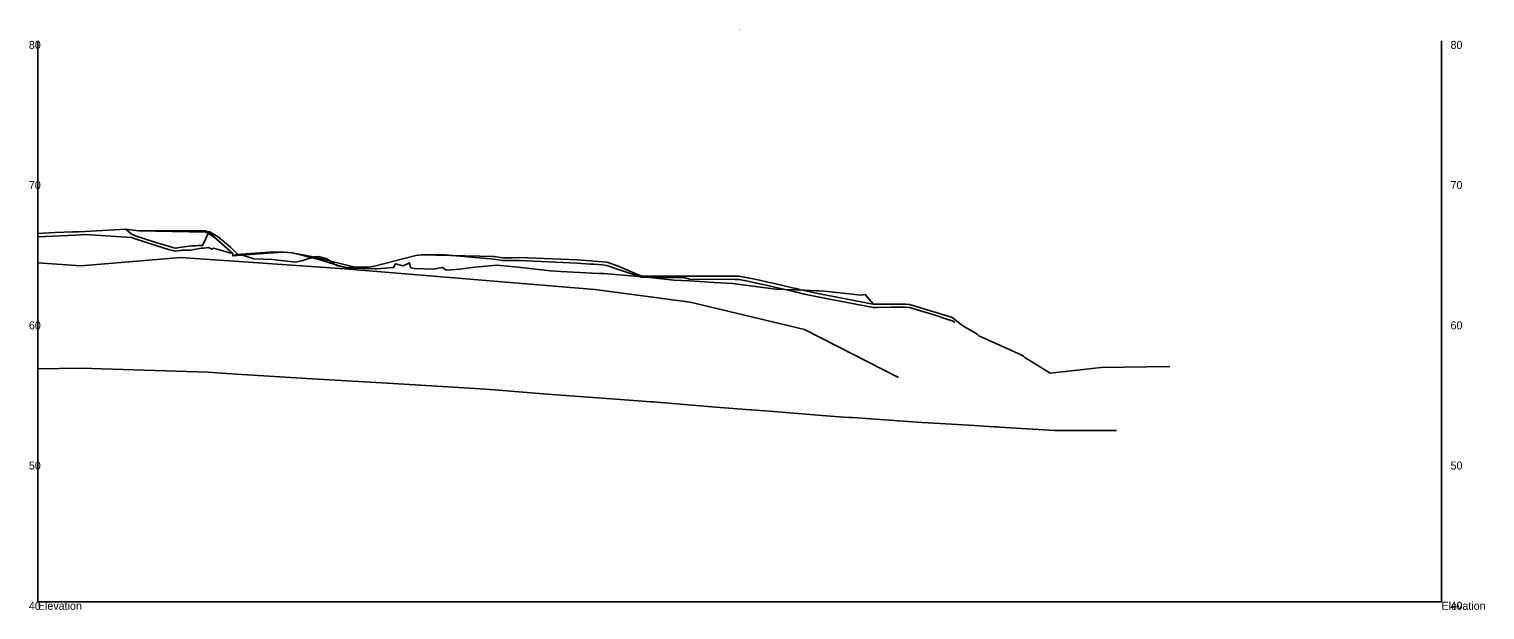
# Model space of a CAD drawing. Extents: x 532503 to 539665, y 6557663 to 6561526.
# Drawn here: x 533984 to 534503, y 6557663 to 6557870 of the extents above; entities that cross this region are included whole.
import ezdxf

# ---------------------------------------------------------------- set-up
doc = ezdxf.new("R2010")
doc.units = 0
for name, color, linetype in [('Default', 7, 'Continuous'), ('lamam', 7, 'Continuous'), ('maapind', 7, 'Continuous'), ('maapind varasem', 7, 'Continuous'), ('P_Profile', 7, 'Continuous'), ('P_SURF_Profile', 7, 'Continuous'), ('vahepiir', 7, 'Continuous')]:
    doc.layers.add(name, color=color, linetype=linetype)

msp = doc.modelspace()

# ---------------------------------------------------------------- linework, layer by layer
at = {"layer": 'Default'}
msp.add_lwpolyline([(533987.25, 6557797.54), (533993.4, 6557797.79), (533999.66, 6557798.05), (534001.76, 6557798.14), (534004.12, 6557798.25), (534018.62, 6557798.99), (534023.1, 6557798.44), (534047.07, 6557798.47), (534049.8, 6557796.71), (534056.65, 6557790.3), (534056.68, 6557789.49), (534069.19, 6557790.51), (534074.73, 6557790.83), (534077.89, 6557790.6), (534084.73, 6557789.27), (534099.76, 6557785.63), (534105.12, 6557785.51), (534107.22, 6557785.86), (534121.92, 6557789.62), (534123.79, 6557789.89), (534149.82, 6557789.25), (534152.87, 6557788.79), (534153.37, 6557788.78), (534153.81, 6557788.78), (534154.39, 6557788.78), (534154.68, 6557788.78), (534155.1, 6557788.78), (534155.7, 6557788.77), (534156, 6557788.77), (534158.87, 6557788.93), (534179.39, 6557788.07), (534184.14, 6557787.73), (534185.28, 6557787.65), (534188.29, 6557787.41), (534189.94, 6557787.27), (534193.7, 6557785.95), (534202.3, 6557782.27), (534210.95, 6557782.27), (534217.57, 6557782.27), (534233.3, 6557782.27), (534237.05, 6557782.27), (534238.75, 6557781.95), (534238.97, 6557781.9), (534243.82, 6557780.93), (534247.71, 6557780.03), (534249.64, 6557779.61), (534256.5, 6557778.02), (534257.4, 6557777.82), (534258.11, 6557777.65), (534259.77, 6557777.27), (534263.84, 6557776.35), (534284.82, 6557772.27), (534285.22, 6557772.27), (534286.49, 6557772.27), (534291.14, 6557772.27), (534293.2, 6557772.27), (534296.46, 6557772.27), (534297.7, 6557772.19), (534312.65, 6557767.65), (534313.28, 6557767.27), (534315.8, 6557765.31), (534317.33, 6557764.23), (534318.38, 6557763.56), (534319.85, 6557762.76), (534320.89, 6557762.22), (534321.17, 6557762.06), (534321.63, 6557761.74), (534321.87, 6557761.54), (534322.22, 6557761.2), (534322.4, 6557760.99), (534337.49, 6557754.26), (534338.42, 6557753.64), (534338.85, 6557753.31), (534347.85, 6557747.74), (534366, 6557749.68), (534390.43, 6557750.08)], dxfattribs=at)
at = {"layer": 'lamam'}
msp.add_lwpolyline([(533987.25, 6557749.22), (534002.59, 6557749.51), (534047.88, 6557748.01), (534054.47, 6557747.61), (534060.04, 6557747.27), (534084.99, 6557745.62), (534113.76, 6557743.95), (534143.01, 6557742.27), (534149.99, 6557741.7), (534154.36, 6557741.36), (534167.27, 6557740.33), (534201.1, 6557737.85), (534205.48, 6557737.52), (534206.7, 6557737.43), (534209.16, 6557737.27), (534228.7, 6557735.62), (534241.05, 6557734.64), (534241.67, 6557734.59), (534252.25, 6557733.73), (534266.68, 6557732.61), (534271.19, 6557732.27), (534276.15, 6557731.92), (534277.48, 6557731.84), (534297.17, 6557730.43), (534302.25, 6557730.16), (534318.99, 6557729.17), (534327.79, 6557728.57), (534328.9, 6557728.51), (534329.73, 6557728.45), (534349.51, 6557727.27), (534352.02, 6557727.27), (534356.77, 6557727.27), (534359.28, 6557727.27), (534366.89, 6557727.27), (534370.27, 6557727.27), (534371.45, 6557727.27)], dxfattribs=at)
at = {"layer": 'maapind'}
msp.add_lwpolyline([(533987.25, 6557797.54), (533993.4, 6557797.79), (533999.66, 6557798.05), (534001.76, 6557798.14), (534004.12, 6557798.25), (534018.62, 6557798.99), (534020.46, 6557797.35), (534020.73, 6557797.2), (534020.96, 6557797.09), (534021.53, 6557796.85), (534022.29, 6557796.57), (534024.83, 6557795.71), (534029.59, 6557794.2), (534033.76, 6557792.94), (534035.32, 6557792.5), (534036.14, 6557792.27), (534039.36, 6557792.74), (534040.35, 6557792.87), (534042.03, 6557793.04), (534043.46, 6557793.13), (534044.32, 6557793.16), (534045.93, 6557793.18), (534048.23, 6557798.17), (534049.17, 6557797.6), (534051.47, 6557796.35), (534055.84, 6557792.64), (534058.32, 6557790.14), (534059.75, 6557789.87), (534064.19, 6557788.48), (534070.85, 6557788.2), (534079.12, 6557787.23), (534081.59, 6557787.85), (534085.7, 6557789.13), (534087.2, 6557789.23), (534090.35, 6557788.5), (534093.61, 6557786.09), (534098.45, 6557785.07), (534107.31, 6557784.92), (534108.03, 6557784.86), (534113.99, 6557785.31), (534114.61, 6557786.69), (534117.37, 6557785.93), (534119.38, 6557786.97), (534119.43, 6557787.09), (534119.46, 6557787.11), (534119.5, 6557787.1), (534120.14, 6557785.27), (534121.37, 6557784.96), (534128.13, 6557784.81), (534131.24, 6557785.39), (534132.86, 6557784.43), (534137.52, 6557784.76), (534142.88, 6557785.47), (534150.78, 6557786.2), (534158.24, 6557785.45), (534169.82, 6557784.13), (534173.53, 6557783.91), (534186.81, 6557783.27), (534188.84, 6557783.19), (534201.14, 6557782.1), (534204.16, 6557781.9), (534213.83, 6557780.82), (534219.47, 6557780.61), (534228.14, 6557780.04), (534234.83, 6557779.62), (534239.19, 6557779.1), (534250.12, 6557777.69), (534260.23, 6557777.26), (534264.55, 6557777.09), (534265.46, 6557777.05), (534268.63, 6557776.81), (534280.55, 6557775.47), (534281.94, 6557775.69), (534284.8, 6557772.4), (534285.22, 6557772.27), (534286.48, 6557772.27), (534291.14, 6557772.27), (534293.2, 6557772.27), (534296.46, 6557772.27), (534297.7, 6557772.19), (534312.65, 6557767.65), (534313.28, 6557767.27), (534315.8, 6557765.31), (534317.33, 6557764.23), (534318.38, 6557763.56), (534319.85, 6557762.76), (534320.89, 6557762.22), (534321.17, 6557762.06), (534321.63, 6557761.74), (534321.87, 6557761.54), (534322.22, 6557761.2), (534322.4, 6557760.99), (534337.49, 6557754.26), (534338.42, 6557753.64), (534338.85, 6557753.31), (534347.85, 6557747.74), (534366, 6557749.68), (534390.43, 6557750.08)], dxfattribs=at)
at = {"layer": 'maapind varasem'}
msp.add_lwpolyline([(533987.25, 6557797.54), (533993.4, 6557797.79), (533999.66, 6557798.05), (534001.76, 6557798.14), (534004.12, 6557798.25), (534018.62, 6557798.99), (534023.1, 6557798.44), (534047.07, 6557798.02), (534049.8, 6557796.37), (534056.65, 6557790.3), (534056.68, 6557789.49), (534069.19, 6557790.51), (534074.73, 6557790.83), (534077.89, 6557790.6), (534084.73, 6557789.27), (534099.76, 6557785.63), (534105.12, 6557785.51), (534107.22, 6557785.86), (534121.92, 6557789.62), (534123.79, 6557789.89), (534149.82, 6557789.25), (534152.87, 6557788.79), (534153.37, 6557788.78), (534153.81, 6557788.78), (534154.39, 6557788.78), (534154.68, 6557788.78), (534155.1, 6557788.78), (534155.7, 6557788.77), (534156, 6557788.77), (534158.87, 6557788.93), (534179.39, 6557788.07), (534184.14, 6557787.73), (534185.28, 6557787.65), (534188.29, 6557787.41), (534189.94, 6557787.27), (534193.7, 6557785.95), (534202.3, 6557782.27), (534210.95, 6557782.27), (534217.57, 6557782.27), (534233.3, 6557782.27), (534237.05, 6557782.27), (534238.75, 6557781.95), (534238.97, 6557781.9), (534243.82, 6557780.93), (534247.71, 6557780.03), (534249.64, 6557779.61), (534256.5, 6557778.02), (534257.4, 6557777.82), (534258.11, 6557777.65), (534259.77, 6557777.27), (534263.84, 6557776.35), (534284.82, 6557772.27), (534285.22, 6557772.27), (534286.49, 6557772.27), (534291.14, 6557772.27), (534293.2, 6557772.27), (534296.46, 6557772.27), (534297.7, 6557772.19), (534312.65, 6557767.65), (534313.28, 6557767.27), (534315.8, 6557765.31), (534317.33, 6557764.23), (534318.38, 6557763.56), (534319.85, 6557762.76), (534320.89, 6557762.22), (534321.17, 6557762.06), (534321.63, 6557761.74), (534321.87, 6557761.54), (534322.22, 6557761.2), (534322.4, 6557760.99), (534337.49, 6557754.26), (534338.42, 6557753.64), (534338.85, 6557753.31), (534347.85, 6557747.74), (534366, 6557749.68), (534390.43, 6557750.08)], dxfattribs=at)
at = {"layer": 'P_Profile'}
for p, q in [((533987.25, 6557666.17), (533987.25, 6557866.17)), ((534487.25, 6557666.17), (534487.25, 6557866.17)), ((533987.25, 6557666.17), (534487.25, 6557666.17))]:
    msp.add_line(p, q, dxfattribs=at)
at = {"layer": 'vahepiir'}
for points in [[(533987.25, 6557796.34), (534000.61, 6557796.92), (534002.59, 6557797.01), (534004.12, 6557797.08), (534020.73, 6557796.06), (534020.96, 6557795.96), (534021.53, 6557795.72), (534022.29, 6557795.44), (534024.83, 6557794.59), (534029.59, 6557793.08), (534033.76, 6557791.84), (534035.32, 6557791.4), (534036.11, 6557791.19), (534036.15, 6557791.17), (534038, 6557791.44), (534038.17, 6557791.46), (534038.22, 6557791.46), (534038.4, 6557791.48), (534038.59, 6557791.49), (534038.73, 6557791.49), (534040.3, 6557791.54), (534041.49, 6557791.54), (534045.56, 6557792.22), (534045.86, 6557792.25), (534046.42, 6557792.3), (534048, 6557792.46), (534049.22, 6557791.94), (534049.8, 6557792.27), (534055.63, 6557790.59), (534056.65, 6557790.3), (534056.68, 6557789.49), (534058, 6557790.03), (534071.4, 6557791.01), (534074.73, 6557790.83), (534077.89, 6557790.6), (534087.75, 6557788.15), (534096.64, 6557785.39), (534099.76, 6557785.31), (534105.12, 6557785.51), (534107.22, 6557785.86), (534121.92, 6557789.62), (534123.79, 6557789.89), (534130.89, 6557790.04), (534149.81, 6557788.37), (534152.86, 6557787.85), (534153.36, 6557787.85), (534153.74, 6557787.85), (534153.8, 6557787.85), (534154.25, 6557787.85), (534154.38, 6557787.85), (534154.67, 6557787.85), (534155.09, 6557787.85), (534155.69, 6557787.84), (534155.99, 6557787.84), (534158.86, 6557787.84), (534158.87, 6557787.84), (534158.87, 6557787.84), (534179.39, 6557786.95), (534184.14, 6557786.6), (534185.28, 6557786.52), (534188.29, 6557786.27), (534189.94, 6557786.13), (534193.7, 6557784.81), (534202.3, 6557781.94), (534206.75, 6557781.89), (534206.91, 6557781.92), (534208.39, 6557781.85), (534217.57, 6557781.68), (534217.81, 6557781.66), (534219.35, 6557781.18), (534235.51, 6557781.1), (534237.05, 6557781.06), (534238.75, 6557780.74), (534238.97, 6557780.69), (534243.82, 6557779.71), (534247.71, 6557778.8), (534249.64, 6557778.38), (534256.5, 6557776.78), (534257.4, 6557776.58), (534258.11, 6557776.41), (534259.77, 6557776.03), (534260.38, 6557775.89), (534262.63, 6557775.36), (534263.84, 6557775.13), (534264.33, 6557775.04), (534284.82, 6557771.15), (534285.22, 6557771.16), (534286.49, 6557771.16), (534291.14, 6557771.19), (534292.2, 6557771.19), (534293.2, 6557771.2), (534293.82, 6557771.2), (534293.9, 6557771.2), (534296.46, 6557771.21), (534297.7, 6557771.13), (534308.04, 6557768.02), (534309.29, 6557767.55), (534310.72, 6557767.03), (534313.28, 6557766.25), (534313.34, 6557766.2), (534313.87, 6557765.78)], [(533987.25, 6557787), (534002.59, 6557785.91), (534038.22, 6557788.92), (534096.64, 6557784.84), (534185.65, 6557777.52), (534219.55, 6557773.04), (534260.38, 6557763.27), (534293.82, 6557746.14)]]:
    msp.add_lwpolyline(points, dxfattribs=at)

# ---------------------------------------------------------------- texts
at = {"layer": 'P_Profile'}
for s, height, p in [('6', 0.4, (534237.11, 6557869.97)), ('80', 2.85, (533984.05, 6557863.32)), ('80', 2.85, (534490.45, 6557863.32)), ('70', 2.85, (533984.05, 6557813.32)), ('70', 2.85, (534490.45, 6557813.32)), ('60', 2.85, (533984.05, 6557763.32)), ('60', 2.85, (534490.45, 6557763.32)), ('50', 2.85, (533984.05, 6557713.32)), ('50', 2.85, (534490.45, 6557713.32)), ('40', 2.85, (533984.05, 6557663.32)), ('-', 0.0001, (533987.25, 6557666.17)), ('40', 2.85, (534490.45, 6557663.32))]:
    msp.add_text(s, height=height, dxfattribs=at).set_placement(p)
at = {"layer": 'P_SURF_Profile'}
for p in [(533987.25, 6557663.32), (534487.25, 6557663.32)]:
    msp.add_text('Elevation', height=2.85, dxfattribs=at).set_placement(p)

doc.saveas('drawing.dxf')
